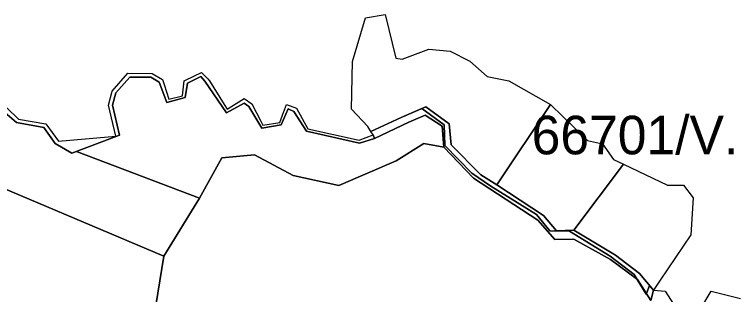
# Model space of a CAD drawing. Extents: x -522079 to -518792, y -1142400 to -1139961.
# Drawn here: x -519443.2 to -519161.2, y -1141371.1 to -1141262.2 of the extents above; entities that cross this region are included whole.
import ezdxf

# ---------------------------------------------------------------- set-up
doc = ezdxf.new("R2010")
doc.units = 0
for name, color, linetype in [('Poz předměty', 7, 'Continuous'), ('Vnitřní kresba', 7, 'Continuous'), ('Značky bodu BP', 7, 'Continuous'), ('Značky budov', 7, 'Continuous')]:
    doc.layers.add(name, color=color, linetype=linetype)

msp = doc.modelspace()

# ---------------------------------------------------------------- linework, layer by layer
at = {"layer": 'Poz předměty'}
for points in [[(-519311.83, -1141280.54), (-519306.82, -1141263.47), (-519299.19, -1141262.23), (-519295.1, -1141279.15), (-519292.59, -1141279.53), (-519282.24, -1141275.71), (-519273.89, -1141276.5), (-519266.36, -1141280.43), (-519259.58, -1141286.33), (-519251.16, -1141288.07), (-519234.97, -1141297.23), (-519255.87, -1141328.5), (-519261.98, -1141324.54), (-519273.62, -1141312.83), (-519274.28, -1141304.73), (-519283.38, -1141298.07), (-519292.93, -1141302.27), (-519304.74, -1141307.68), (-519305.93, -1141305.82), (-519312.28, -1141299.01)], [(-519206.65, -1141320.44), (-519225.91, -1141346.11), (-519232.62, -1141346.31), (-519237.64, -1141340.3), (-519255.87, -1141328.5), (-519234.97, -1141297.23), (-519220.59, -1141311.22), (-519214.82, -1141312.52), (-519210.53, -1141318.6)], [(-519206.65, -1141320.44), (-519189.49, -1141328.56), (-519183.26, -1141328.59), (-519179.55, -1141333.52), (-519180.48, -1141347.87), (-519192.3, -1141365.49), (-519194.96, -1141369.43), (-519200.4, -1141362.91), (-519209.66, -1141355.81), (-519225.91, -1141346.11)]]:
    msp.add_lwpolyline(points, close=True, dxfattribs=at)
at = {"layer": 'Vnitřní kresba'}
for points in [[(-519446.22, -1141298.48), (-519441.7, -1141302.87), (-519430.99, -1141304.77), (-519426.16, -1141311.48), (-519403.83, -1141309.49), (-519406.68, -1141297.5), (-519405.2, -1141292.02), (-519399.13, -1141285.07), (-519389.78, -1141285.13), (-519385.69, -1141287.55), (-519385.12, -1141289.38), (-519383.31, -1141295.11), (-519377.88, -1141293.85), (-519377.66, -1141291.53), (-519377.33, -1141288.06), (-519373.33, -1141286.11), (-519370.55, -1141284.76), (-519368.04, -1141287.17), (-519367.51, -1141288.01), (-519361.74, -1141297.24), (-519360.6, -1141299.07), (-519359.18, -1141298.18), (-519353.95, -1141294.93), (-519351.06, -1141296.96), (-519347.55, -1141303.63), (-519346.7, -1141305.23), (-519340.12, -1141304.19), (-519339.07, -1141301.4), (-519337.51, -1141297.26), (-519333.7, -1141298.67), (-519329.18, -1141306.68), (-519309.3, -1141311.02), (-519303.86, -1141309.05), (-519303.35, -1141310.46), (-519309.12, -1141312.18), (-519329.81, -1141307.56), (-519334.73, -1141299.89), (-519336.85, -1141298.85), (-519339.54, -1141305.07), (-519347.17, -1141306.35), (-519352.22, -1141297.98), (-519354, -1141296.72), (-519360.8, -1141300.45), (-519369.21, -1141288.13), (-519370.85, -1141286.3), (-519376.04, -1141288.86), (-519376.93, -1141294.5), (-519383.98, -1141296.49), (-519386.96, -1141288.54), (-519390.2, -1141286.63), (-519398.45, -1141286.57), (-519403.84, -1141292.74), (-519405.13, -1141297.52), (-519402.36, -1141309.19), (-519420.99, -1141316.12), (-519427.38, -1141312.36), (-519431.85, -1141306.14), (-519442.41, -1141304.27), (-519446.9, -1141300.29)], [(-519195.98, -1141373.38), (-519194.96, -1141369.43), (-519190.42, -1141369.81), (-519187.2, -1141374.82)], [(-519180.54, -1141383.29), (-519172.49, -1141369.75), (-519161.16, -1141372.68)]]:
    msp.add_lwpolyline(points, dxfattribs=at)
msp.add_lwpolyline([(-519225.91, -1141346.11), (-519209.66, -1141355.81), (-519200.4, -1141362.91), (-519194.96, -1141369.43), (-519195.98, -1141373.38), (-519201.22, -1141365.24), (-519211.68, -1141357.48), (-519225.95, -1141349.55), (-519233.32, -1141349.64), (-519239.84, -1141342.13), (-519264.89, -1141325.79), (-519276.42, -1141313.78), (-519277.01, -1141305.57), (-519283.62, -1141301.34), (-519290.01, -1141304.08), (-519303.35, -1141310.46), (-519303.86, -1141309.05), (-519304.74, -1141307.68), (-519292.93, -1141302.27), (-519283.38, -1141298.07), (-519274.28, -1141304.73), (-519273.62, -1141312.83), (-519261.98, -1141324.54), (-519255.87, -1141328.5), (-519237.64, -1141340.3), (-519232.62, -1141346.31)], close=True, dxfattribs=at)
at = {"layer": 'Značky bodu BP'}
msp.add_lwpolyline([(-519305.93, -1141305.82), (-519312.28, -1141299.01), (-519311.83, -1141280.54), (-519306.82, -1141263.47), (-519299.19, -1141262.23), (-519295.1, -1141279.15), (-519292.59, -1141279.53), (-519282.24, -1141275.71), (-519273.89, -1141276.5), (-519266.36, -1141280.43), (-519259.58, -1141286.33), (-519251.16, -1141288.07), (-519234.97, -1141297.23), (-519220.59, -1141311.22), (-519214.82, -1141312.52), (-519210.53, -1141318.6), (-519206.65, -1141320.44), (-519189.49, -1141328.56), (-519183.26, -1141328.59), (-519179.55, -1141333.52), (-519180.48, -1141347.87), (-519192.3, -1141365.49), (-519194.96, -1141369.43), (-519196.47, -1141367.62), (-519197.68, -1141370.73), (-519197.76, -1141370.93), (-519201.3, -1141365.18), (-519202.46, -1141363.29), (-519211.75, -1141356.23), (-519227.56, -1141346.51), (-519235.22, -1141346.32), (-519240.47, -1141339.97), (-519258.15, -1141328.91), (-519265.54, -1141323.87), (-519275.96, -1141313.17), (-519276.3, -1141305.09), (-519284.95, -1141298.76), (-519292.93, -1141302.27), (-519304.74, -1141307.68)], close=True, dxfattribs=at)
for points in [[(-519446.22, -1141298.48), (-519441.7, -1141302.87), (-519430.99, -1141304.77), (-519426.16, -1141311.48), (-519403.83, -1141309.49), (-519406.68, -1141297.5), (-519405.2, -1141292.02), (-519399.13, -1141285.07), (-519389.78, -1141285.13), (-519385.69, -1141287.55), (-519385.12, -1141289.38), (-519383.31, -1141295.11), (-519377.88, -1141293.85), (-519377.66, -1141291.53), (-519377.33, -1141288.06), (-519373.33, -1141286.11), (-519370.55, -1141284.76), (-519368.04, -1141287.17), (-519367.51, -1141288.01), (-519361.74, -1141297.24), (-519360.6, -1141299.07), (-519359.18, -1141298.18), (-519353.95, -1141294.93), (-519351.06, -1141296.96), (-519347.55, -1141303.63), (-519346.7, -1141305.23), (-519340.12, -1141304.19), (-519339.07, -1141301.4), (-519337.51, -1141297.26), (-519333.7, -1141298.67), (-519329.18, -1141306.68), (-519309.3, -1141311.02), (-519303.86, -1141309.05), (-519304.74, -1141307.68), (-519292.93, -1141302.27), (-519284.95, -1141298.76), (-519276.3, -1141305.09), (-519275.96, -1141313.17), (-519265.54, -1141323.87), (-519258.15, -1141328.91), (-519240.47, -1141339.97), (-519235.22, -1141346.32), (-519227.56, -1141346.51), (-519211.75, -1141356.23), (-519202.46, -1141363.29), (-519201.3, -1141365.18), (-519197.76, -1141370.93), (-519197.68, -1141370.73), (-519196.47, -1141367.62), (-519194.96, -1141369.43), (-519190.42, -1141369.81), (-519187.2, -1141374.82)], [(-519180.54, -1141383.29), (-519172.49, -1141369.75), (-519161.16, -1141372.68)]]:
    msp.add_lwpolyline(points, dxfattribs=at)
at = {"layer": 'Značky budov'}
for points in [[(-519419.15, -1141315.48), (-519420.99, -1141316.12), (-519402.36, -1141309.19), (-519405.13, -1141297.52), (-519403.84, -1141292.74), (-519398.45, -1141286.57), (-519390.2, -1141286.63), (-519386.96, -1141288.54), (-519383.98, -1141296.49), (-519376.93, -1141294.5), (-519376.04, -1141288.86), (-519370.85, -1141286.3), (-519369.21, -1141288.13), (-519360.8, -1141300.45), (-519354, -1141296.72), (-519352.22, -1141297.98), (-519347.17, -1141306.35), (-519339.54, -1141305.07), (-519336.85, -1141298.85), (-519334.73, -1141299.89), (-519329.81, -1141307.56), (-519309.12, -1141312.18), (-519303.35, -1141310.46), (-519290.01, -1141304.08), (-519283.62, -1141301.34), (-519277.01, -1141305.57), (-519276.42, -1141313.78), (-519284.21, -1141312.41), (-519294.89, -1141319.05), (-519317.19, -1141328.69), (-519334.98, -1141324.76), (-519350.02, -1141316.82), (-519362.63, -1141317.99), (-519371.28, -1141333.68)], [(-519385.2, -1141356.16), (-519465.42, -1141322.27), (-519465.26, -1141311.18), (-519465.25, -1141309.34), (-519466.74, -1141308.54), (-519468.94, -1141304.33), (-519461.31, -1141303.85), (-519449.71, -1141299.98), (-519446.9, -1141300.29), (-519442.41, -1141304.27), (-519431.85, -1141306.14), (-519427.38, -1141312.36), (-519420.99, -1141316.12), (-519419.15, -1141315.48), (-519371.28, -1141333.68)], [(-519494.92, -1141380.6), (-519493.9, -1141370.24), (-519484.66, -1141353.81), (-519477.91, -1141348.96), (-519470.8, -1141337.38), (-519465.42, -1141322.27), (-519385.2, -1141356.16), (-519392.16, -1141399.31), (-519386.73, -1141417.35), (-519402.53, -1141416.1), (-519450.75, -1141420.94), (-519466.91, -1141416.21), (-519490.7, -1141404.57), (-519496.45, -1141402.69), (-519489.99, -1141393.96), (-519488.36, -1141388.76)]]:
    msp.add_lwpolyline(points, close=True, dxfattribs=at)
msp.add_lwpolyline([(-519392.16, -1141399.31), (-519385.2, -1141356.16), (-519371.28, -1141333.68), (-519362.63, -1141317.99), (-519350.02, -1141316.82), (-519334.98, -1141324.76), (-519317.19, -1141328.69), (-519294.89, -1141319.05), (-519284.21, -1141312.41), (-519276.42, -1141313.78), (-519264.89, -1141325.79), (-519239.84, -1141342.13), (-519233.32, -1141349.64), (-519225.95, -1141349.55), (-519211.68, -1141357.48), (-519201.22, -1141365.24), (-519195.98, -1141373.38)], dxfattribs=at)

# ---------------------------------------------------------------- texts
at = {"layer": 'Značky bodu BP'}
msp.add_text('66701/V.', height=15, rotation=360, dxfattribs=at).set_placement((-519242.3, -1141316.58))

doc.saveas('drawing.dxf')
